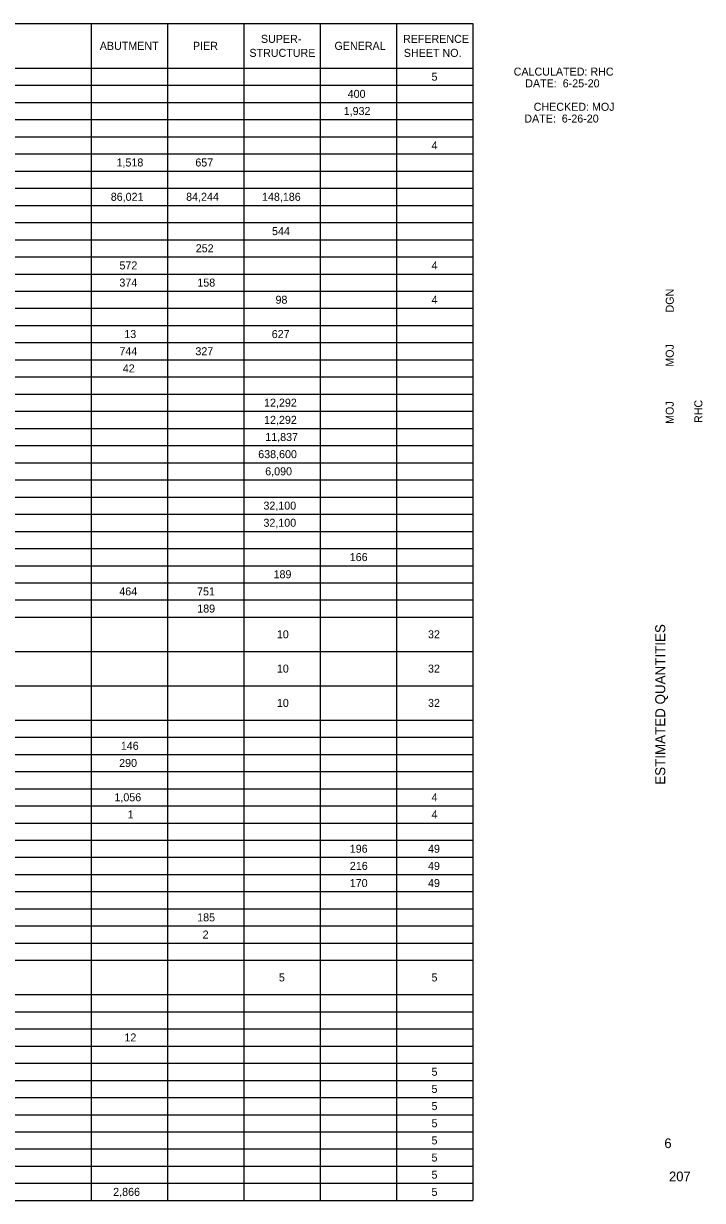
# Model space of a CAD drawing. Extents: x 3.1 to 33.4, y 0.7 to 21.3.
# Drawn here: x 21.53 to 33.41, y 0.75 to 21.33 of the extents above; entities that cross this region are included whole.
import ezdxf

# ---------------------------------------------------------------- set-up
doc = ezdxf.new("R2010")
doc.units = 0
for name, color, linetype in [('BR_P_Gen_Text', 7, 'Continuous'), ('Default', 7, 'Continuous'), ('SH_Data', 7, 'Continuous'), ('SH_Text', 7, 'Continuous')]:
    doc.layers.add(name, color=color, linetype=linetype)

msp = doc.modelspace()

# ---------------------------------------------------------------- linework, layer by layer
at = {"layer": 'SH_Data'}
for p, q in [((3.061, 21.33), (29.386, 21.33)), ((22.711, 21.33), (22.711, 0.75)), ((24.046, 21.33), (24.046, 0.75)), ((25.381, 21.33), (25.381, 0.75)), ((26.716, 21.33), (26.716, 0.75)), ((28.051, 21.33), (28.051, 0.75)), ((29.386, 21.33), (29.386, 20.55)), ((3.061, 20.55), (29.386, 20.55)), ((29.386, 20.55), (29.386, 0.75)), ((3.061, 20.25), (29.386, 20.25)), ((3.061, 19.95), (29.386, 19.95)), ((3.061, 19.65), (29.386, 19.65)), ((3.061, 19.35), (29.386, 19.35)), ((3.061, 19.05), (29.386, 19.05)), ((3.061, 18.75), (29.386, 18.75)), ((3.061, 18.45), (29.386, 18.45)), ((3.061, 18.15), (29.386, 18.15)), ((3.061, 17.85), (29.386, 17.85)), ((3.061, 17.55), (29.386, 17.55)), ((3.061, 17.25), (29.386, 17.25)), ((3.061, 16.95), (29.386, 16.95)), ((3.061, 16.65), (29.386, 16.65)), ((3.061, 16.35), (29.386, 16.35)), ((3.061, 16.05), (29.386, 16.05)), ((3.061, 15.75), (29.386, 15.75)), ((3.061, 15.45), (29.386, 15.45)), ((3.061, 15.15), (29.386, 15.15)), ((3.061, 14.85), (29.386, 14.85)), ((3.061, 14.55), (29.386, 14.55)), ((3.061, 14.25), (29.386, 14.25)), ((3.061, 13.95), (29.386, 13.95)), ((3.061, 13.65), (29.386, 13.65)), ((3.061, 13.35), (29.386, 13.35)), ((3.061, 13.05), (29.386, 13.05)), ((3.061, 12.75), (29.386, 12.75)), ((3.061, 12.45), (29.386, 12.45)), ((3.061, 12.15), (29.386, 12.15)), ((3.061, 11.85), (29.386, 11.85)), ((3.061, 11.55), (29.386, 11.55)), ((3.061, 11.25), (29.386, 11.25)), ((3.061, 10.95), (29.386, 10.95)), ((3.061, 10.35), (29.386, 10.35)), ((3.061, 9.75), (29.386, 9.75)), ((3.061, 9.15), (29.386, 9.15)), ((3.061, 8.85), (29.386, 8.85)), ((3.061, 8.55), (29.386, 8.55)), ((3.061, 8.25), (29.386, 8.25)), ((3.061, 7.95), (29.386, 7.95)), ((3.061, 7.65), (29.386, 7.65)), ((3.061, 7.35), (29.386, 7.35)), ((3.061, 7.05), (29.386, 7.05)), ((3.061, 6.75), (29.386, 6.75)), ((3.061, 6.45), (29.386, 6.45)), ((3.061, 6.15), (29.386, 6.15)), ((3.061, 5.85), (29.386, 5.85)), ((3.061, 5.55), (29.386, 5.55)), ((3.061, 5.25), (29.386, 5.25)), ((3.061, 4.95), (29.386, 4.95)), ((3.061, 4.35), (29.386, 4.35)), ((3.061, 4.05), (29.386, 4.05)), ((3.061, 3.75), (29.386, 3.75)), ((3.061, 3.45), (29.386, 3.45)), ((3.061, 3.15), (29.386, 3.15)), ((3.061, 2.85), (29.386, 2.85)), ((3.061, 2.55), (29.386, 2.55)), ((3.061, 2.25), (29.386, 2.25)), ((3.061, 1.95), (29.386, 1.95)), ((3.061, 1.65), (29.386, 1.65)), ((3.061, 1.35), (29.386, 1.35)), ((3.061, 1.05), (29.386, 1.05)), ((3.061, 0.75), (29.386, 0.75))]:
    msp.add_line(p, q, dxfattribs=at)

# ---------------------------------------------------------------- texts
at = {"layer": 'BR_P_Gen_Text'}
for s, p in [('6', (32.739, 1.665)), ('207', (32.82, 1.085))]:
    msp.add_text(s, height=0.17, dxfattribs=at).set_placement(p)
at = {"layer": 'Default'}
for s, p in [('CALCULATED: RHC', (30.103, 20.419)), ('DATE:  6-25-20', (30.305, 20.214)), ('CHECKED: MOJ', (30.453, 19.804)), ('DATE:  6-26-20', (30.289, 19.598))]:
    msp.add_text(s, height=0.14, dxfattribs=at).set_placement(p)
at = {"layer": 'SH_Data'}
for s, height, p in [('DGN', 0.14, (32.903, 16.277)), ('MOJ', 0.14, (32.903, 15.329)), ('MOJ', 0.14, (32.903, 14.329)), ('RHC', 0.14, (33.403, 14.344)), ('ESTIMATED QUANTITIES', 0.175, (32.754, 8.019))]:
    msp.add_text(s, height=height, rotation=90, dxfattribs=at).set_placement(p)
at = {"layer": 'SH_Text'}
for s, p in [('ABUTMENT', (22.862, 20.87)), ('PIER', (24.492, 20.87)), ('SUPER-', (25.681, 20.992)), ('GENERAL', (26.968, 20.87)), ('REFERENCE', (28.166, 20.992)), ('STRUCTURE', (25.48, 20.747)), ('SHEET NO.', (28.181, 20.747)), ('5', (28.665, 20.33)), ('400', (27.199, 20.03)), ('1,932', (27.129, 19.73)), ('4', (28.666, 19.13)), ('1,518', (23.155, 18.83)), ('657', (24.534, 18.83)), ('86,021', (23.054, 18.23)), ('84,244', (24.373, 18.23)), ('148,186', (25.7, 18.23)), ('544', (25.875, 17.63)), ('252', (24.541, 17.33)), ('572', (23.206, 17.03)), ('4', (28.666, 17.03)), ('374', (23.205, 16.73)), ('158', (24.569, 16.73)), ('98', (25.936, 16.43)), ('4', (28.666, 16.43)), ('13', (23.291, 15.83)), ('627', (25.87, 15.83)), ('744', (23.206, 15.53)), ('327', (24.535, 15.53)), ('42', (23.265, 15.23)), ('12,292', (25.736, 14.63)), ('12,292', (25.736, 14.33)), ('11,837', (25.757, 14.03)), ('638,600', (25.634, 13.73)), ('6,090', (25.756, 13.43)), ('32,100', (25.725, 12.83)), ('32,100', (25.725, 12.53)), ('166', (27.235, 11.93)), ('189', (25.902, 11.63)), ('464', (23.204, 11.33)), ('751', (24.564, 11.33)), ('189', (24.567, 11.03)), ('10', (25.96, 10.58)), ('32', (28.604, 10.58)), ('10', (25.96, 9.98)), ('32', (28.604, 9.98)), ('10', (25.96, 9.38)), ('32', (28.604, 9.38)), ('146', (23.23, 8.63)), ('290', (23.201, 8.33)), ('1,056', (23.118, 7.73)), ('4', (28.666, 7.73)), ('1', (23.349, 7.43)), ('4', (28.666, 7.43)), ('196', (27.235, 6.83)), ('49', (28.604, 6.83)), ('216', (27.237, 6.53)), ('49', (28.604, 6.53)), ('170', (27.235, 6.23)), ('49', (28.604, 6.23)), ('185', (24.566, 5.63)), ('2', (24.661, 5.33)), ('5', (25.995, 4.58)), ('5', (28.665, 4.58)), ('12', (23.293, 3.53)), ('5', (28.665, 2.93)), ('5', (28.665, 2.63)), ('5', (28.665, 2.33)), ('5', (28.665, 2.03)), ('5', (28.665, 1.73)), ('5', (28.665, 1.43)), ('5', (28.665, 1.13)), ('2,866', (23.097, 0.83)), ('5', (28.665, 0.83))]:
    msp.add_text(s, height=0.14, dxfattribs=at).set_placement(p)

doc.saveas('drawing.dxf')
